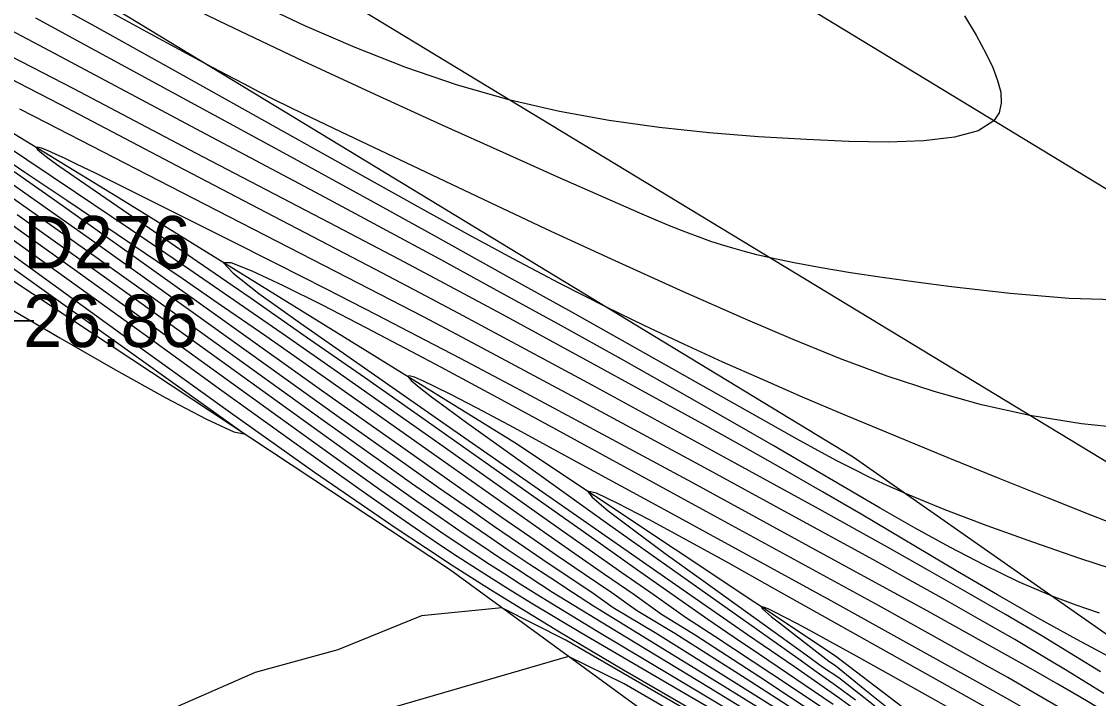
# Model space of a CAD drawing. Extents: x 2356077 to 2359823, y 225951 to 227822.
# Drawn here: x 2356489 to 2356540.3, y 227327.7 to 227360 of the extents above; entities that cross this region are included whole.
import ezdxf

# ---------------------------------------------------------------- set-up
doc = ezdxf.new("R2010")
doc.units = 0
for name, color, linetype in [('DTM Contours Major', 7, 'Continuous'), ('DTM Contours Minor', 7, 'Continuous'), ('Exist DTM Crownline', 7, 'Continuous'), ('Exist DTM Regular Point CELL', 7, 'Continuous'), ('Exist DTM Regular Point Cogo Elevation', 7, 'Continuous'), ('Exist DTM Regular Point Cogo Number', 7, 'Continuous'), ('Exist Roads EOP', 7, 'Continuous'), ('PH Exist DTM Breakline', 7, 'Continuous')]:
    doc.layers.add(name, color=color, linetype=linetype)

msp = doc.modelspace()

# ---------------------------------------------------------------- linework, layer by layer
at = {"layer": 'DTM Contours Major'}
for points in [[(2356541.622, 227333.644), (2356539.425, 227334.374), (2356537.196, 227335.142), (2356535.016, 227335.927), (2356532.964, 227336.708), (2356531.12, 227337.463), (2356530.235, 227337.854), (2356529.412, 227338.238), (2356528.631, 227338.624), (2356527.871, 227339.018), (2356527.11, 227339.427), (2356525.955, 227340.066), (2356518.48, 227344.278), (2356515.343, 227346.036), (2356512.075, 227347.86), (2356508.788, 227349.686), (2356505.591, 227351.451), (2356501.795, 227353.527), (2356492.468, 227358.61), (2356489.639, 227360.142)], [(2356540.42, 227327.183), (2356539.403, 227327.781), (2356538.375, 227328.375), (2356537.336, 227328.969), (2356536.282, 227329.565), (2356534.883, 227330.349), (2356532.009, 227331.942), (2356527.538, 227334.39), (2356520.938, 227337.985), (2356516.065, 227340.621), (2356513.037, 227342.245), (2356511.48, 227343.072), (2356509.884, 227343.914), (2356508.242, 227344.773), (2356505.891, 227345.99), (2356503.496, 227347.217), (2356501.118, 227348.425), (2356498.815, 227349.587), (2356494.676, 227351.661), (2356492.486, 227352.747), (2356491.578, 227353.188), (2356491.035, 227353.446), (2356490.568, 227353.662), (2356490.185, 227353.83), (2356489.897, 227353.943), (2356489.714, 227353.996), (2356489.646, 227353.983), (2356489.714, 227353.884), (2356489.926, 227353.701), (2356490.268, 227353.441), (2356490.729, 227353.109), (2356491.948, 227352.26), (2356495.057, 227350.126), (2356497.332, 227348.558), (2356499.851, 227346.815), (2356502.535, 227344.95), (2356505.306, 227343.017), (2356508.087, 227341.07), (2356510.798, 227339.161), (2356516.565, 227335.075), (2356518.337, 227333.823), (2356521.693, 227331.468), (2356522.935, 227330.617), (2356524.157, 227329.802), (2356527.661, 227327.416)], [(2356486.713, 227352.852), (2356489.333, 227351.009), (2356491.955, 227349.147), (2356494.546, 227347.294), (2356503.346, 227340.965), (2356506.203, 227338.927), (2356507.559, 227337.968), (2356508.881, 227337.041), (2356510.18, 227336.141), (2356511.173, 227335.46), (2356512.167, 227334.786), (2356513.171, 227334.114), (2356514.192, 227333.441), (2356515.236, 227332.763), (2356516.233, 227332.105), (2356522.308, 227328.367), (2356524.382, 227327.08)], [(2356488.037, 227346.502), (2356490.783, 227344.889), (2356493.442, 227343.365), (2356495.832, 227342.038), (2356497.77, 227341.015), (2356499.075, 227340.405), (2356499.564, 227340.316), (2356485.329, 227350.492)], [(2356533.057, 227318.89), (2356530.455, 227321.093), (2356529.82, 227321.83), (2356514.909, 227330.476), (2356511.858, 227332.014), (2356508.024, 227331.625), (2356504.035, 227330.014), (2356500.093, 227328.926), (2356496.11, 227327.175), (2356492.183, 227325.43), (2356488.37, 227323.972), (2356485.562, 227323.168), (2356482.844, 227322.567), (2356480.208, 227322.059), (2356477.647, 227321.533), (2356475.152, 227320.881), (2356472.716, 227319.993), (2356469.729, 227318.43), (2356466.769, 227316.422), (2356463.782, 227314.071), (2356460.714, 227311.474), (2356457.512, 227308.733), (2356454.123, 227305.947)]]:
    msp.add_lwpolyline(points, dxfattribs=at)
at = {"layer": 'DTM Contours Minor'}
for points in [[(2356541.589, 227346.691), (2356538.927, 227346.768), (2356536.11, 227347.006), (2356533.312, 227347.331), (2356531.615, 227347.55), (2356530.007, 227347.774), (2356528.496, 227348.002), (2356527.093, 227348.234), (2356525.81, 227348.471), (2356524.656, 227348.711), (2356524.024, 227348.859), (2356523.435, 227349.01), (2356522.878, 227349.166), (2356522.346, 227349.328), (2356521.829, 227349.499), (2356521.319, 227349.678), (2356520.639, 227349.934), (2356519.942, 227350.211), (2356519.217, 227350.513), (2356518.451, 227350.842), (2356516.749, 227351.589), (2356514.508, 227352.58), (2356511.917, 227353.734), (2356509.011, 227355.043), (2356505.824, 227356.501), (2356502.391, 227358.1), (2356498.745, 227359.834), (2356494.329, 227361.983)], [(2356542.615, 227335.394), (2356540.004, 227336.42), (2356537.884, 227337.262), (2356535.577, 227338.188), (2356533.145, 227339.174), (2356530.65, 227340.199), (2356528.153, 227341.242), (2356526.207, 227342.07), (2356524.293, 227342.9), (2356522.406, 227343.739), (2356520.539, 227344.592), (2356518.688, 227345.466), (2356516.847, 227346.365), (2356514.635, 227347.489), (2356512.427, 227348.651), (2356510.219, 227349.845), (2356508.009, 227351.064), (2356505.795, 227352.302), (2356498.687, 227356.289), (2356495.581, 227358.022), (2356492.328, 227359.827), (2356489.028, 227361.645)], [(2356540.408, 227328.965), (2356539.229, 227329.698), (2356537.621, 227330.67), (2356535.887, 227331.691), (2356534.06, 227332.746), (2356532.171, 227333.821), (2356530.25, 227334.902), (2356526.99, 227336.713), (2356522.996, 227338.908), (2356516.173, 227342.63), (2356514.065, 227343.772), (2356511.939, 227344.918), (2356509.805, 227346.06), (2356507.678, 227347.189), (2356505.83, 227348.16), (2356500.251, 227351.065), (2356496.385, 227353.083), (2356490.79, 227356.026), (2356488.796, 227357.068), (2356486.725, 227358.141), (2356484.568, 227359.245), (2356481.495, 227360.792)], [(2356541.101, 227329.529), (2356539.288, 227330.494), (2356537.412, 227331.54), (2356535.506, 227332.635), (2356533.603, 227333.75), (2356528.998, 227336.476), (2356527.155, 227337.551), (2356525.282, 227338.626), (2356523.339, 227339.722), (2356521.254, 227340.885), (2356519.083, 227342.085), (2356516.764, 227343.358), (2356514.343, 227344.678), (2356511.869, 227346.018), (2356509.39, 227347.349), (2356506.953, 227348.646), (2356503.645, 227350.386), (2356497.269, 227353.714), (2356491.447, 227356.771), (2356489.444, 227357.812), (2356487.398, 227358.864), (2356485.304, 227359.924), (2356482.938, 227361.1)], [(2356540.376, 227331.753), (2356539.248, 227332.135), (2356538.111, 227332.567), (2356536.505, 227333.259), (2356534.879, 227334.042), (2356533.237, 227334.901), (2356531.579, 227335.817), (2356529.909, 227336.774), (2356524.798, 227339.757), (2356522.978, 227340.809), (2356520.354, 227342.306), (2356517.575, 227343.87), (2356514.704, 227345.467), (2356511.803, 227347.065), (2356508.934, 227348.63), (2356506.161, 227350.128), (2356503.221, 227351.7), (2356497.542, 227354.718), (2356490.549, 227358.452), (2356488.189, 227359.699), (2356485.846, 227360.92)], [(2356541.99, 227340.539), (2356539.511, 227340.796), (2356537.052, 227341.191), (2356534.741, 227341.704), (2356532.477, 227342.335), (2356530.24, 227343.071), (2356528.008, 227343.9), (2356525.76, 227344.809), (2356523.476, 227345.783), (2356520.379, 227347.151), (2356517.265, 227348.563), (2356514.217, 227349.973), (2356511.32, 227351.332), (2356504.212, 227354.702), (2356502.378, 227355.584), (2356501.015, 227356.259), (2356500.303, 227356.619), (2356499.548, 227357.009), (2356498.729, 227357.439), (2356497.828, 227357.918), (2356495.127, 227359.38), (2356491.969, 227361.113)], [(2356533.931, 227360.26), (2356534.483, 227359.332), (2356534.965, 227358.444), (2356535.275, 227357.793), (2356535.511, 227357.18), (2356535.655, 227356.611), (2356535.685, 227356.095), (2356535.583, 227355.638), (2356535.329, 227355.249), (2356534.577, 227354.775), (2356533.445, 227354.466), (2356531.996, 227354.296), (2356530.295, 227354.239), (2356528.405, 227354.266), (2356526.39, 227354.352), (2356524.096, 227354.491), (2356521.749, 227354.68), (2356519.371, 227354.936), (2356516.983, 227355.27), (2356514.605, 227355.697), (2356512.261, 227356.231), (2356509.745, 227356.949), (2356507.282, 227357.794), (2356504.858, 227358.747), (2356502.461, 227359.79), (2356500.079, 227360.905)], [(2356540.576, 227327.918), (2356539.707, 227328.461), (2356538.824, 227329.003), (2356537.924, 227329.547), (2356536.324, 227330.494), (2356534.678, 227331.446), (2356532.999, 227332.4), (2356531.296, 227333.354), (2356529.581, 227334.304), (2356526.38, 227336.06), (2356521.925, 227338.484), (2356515.424, 227342.003), (2356511.83, 227343.932), (2356509.991, 227344.909), (2356508.122, 227345.893), (2356506.059, 227346.968), (2356503.967, 227348.049), (2356495.479, 227352.404), (2356490.177, 227355.132), (2356488.868, 227355.799)], [(2356486.866, 227354.97), (2356491.529, 227351.849), (2356494.101, 227350.113), (2356496.682, 227348.356), (2356499.129, 227346.674), (2356501.583, 227344.974), (2356504.025, 227343.27), (2356506.433, 227341.579), (2356508.788, 227339.919), (2356514.414, 227335.932), (2356516.02, 227334.798), (2356517.589, 227333.698), (2356519.129, 227332.631), (2356520.62, 227331.562), (2356522.019, 227330.668), (2356524.739, 227328.867), (2356527.392, 227327.093)], [(2356487.283, 227354.045), (2356489.115, 227352.804), (2356491.113, 227351.467), (2356493.019, 227350.182), (2356494.848, 227348.942), (2356496.614, 227347.736), (2356498.331, 227346.556), (2356500.599, 227344.984), (2356502.805, 227343.446), (2356504.947, 227341.942), (2356509.047, 227339.046), (2356513.92, 227335.6), (2356515.343, 227334.604), (2356516.754, 227333.626), (2356518.16, 227332.665), (2356519.483, 227331.705), (2356521.083, 227330.72), (2356524.12, 227328.745), (2356525.632, 227327.756), (2356527.13, 227326.766)], [(2356487.634, 227352.853), (2356489.917, 227351.247), (2356492.171, 227349.65), (2356494.387, 227348.071), (2356504.099, 227341.116), (2356507.296, 227338.846), (2356508.842, 227337.758), (2356510.36, 227336.697), (2356511.515, 227335.897), (2356512.663, 227335.107), (2356513.815, 227334.325), (2356514.978, 227333.546), (2356516.161, 227332.766), (2356517.179, 227332.036), (2356519.173, 227330.838), (2356522.907, 227328.503), (2356524.792, 227327.315)], [(2356488.596, 227352.83), (2356490.527, 227351.473), (2356494.261, 227348.827), (2356503.376, 227342.325), (2356507.025, 227339.736), (2356510.557, 227337.248), (2356511.882, 227336.322), (2356513.191, 227335.412), (2356514.493, 227334.516), (2356515.796, 227333.63), (2356517.108, 227332.752), (2356518.285, 227331.894), (2356520.109, 227330.799), (2356523.509, 227328.637), (2356525.21, 227327.547), (2356526.892, 227326.448), (2356528.667, 227325.395), (2356529.902, 227324.427), (2356531.181, 227323.461), (2356532.454, 227322.514), (2356533.695, 227321.564), (2356534.902, 227320.614), (2356535.995, 227319.683), (2356541.028, 227315.213)], [(2356488.124, 227350.556), (2356491.479, 227348.162), (2356494.837, 227345.745), (2356501.176, 227341.162), (2356503.964, 227339.152), (2356506.091, 227337.635), (2356507.078, 227336.94), (2356508.028, 227336.278), (2356508.954, 227335.643), (2356509.867, 227335.025), (2356510.57, 227334.558), (2356511.279, 227334.093), (2356511.998, 227333.628), (2356512.734, 227333.159), (2356513.492, 227332.683), (2356514.278, 227332.196), (2356516.438, 227330.886), (2356521.183, 227328.057), (2356523.648, 227326.576)], [(2356488.744, 227350.773), (2356491.734, 227348.645), (2356494.707, 227346.512), (2356502.906, 227340.598), (2356505.469, 227338.761), (2356506.659, 227337.916), (2356507.805, 227337.11), (2356508.921, 227336.335), (2356510.018, 227335.583), (2356510.861, 227335.013), (2356511.708, 227334.448), (2356512.567, 227333.883), (2356514.283, 227332.768), (2356517.33, 227330.892), (2356521.729, 227328.224), (2356523.995, 227326.837)], [(2356486.423, 227350.365), (2356490.453, 227347.46), (2356494.618, 227344.439), (2356498.812, 227341.414), (2356502.93, 227338.493), (2356506.866, 227335.785), (2356508.214, 227334.886), (2356509.538, 227334.021), (2356510.891, 227333.156), (2356511.568, 227332.731), (2356514.614, 227330.866), (2356517.666, 227329.058), (2356520.679, 227327.307), (2356523.605, 227325.612), (2356526.398, 227323.973), (2356529.013, 227322.389), (2356530.127, 227321.69), (2356531.198, 227320.999), (2356532.07, 227320.375), (2356533.323, 227319.314), (2356533.923, 227318.793), (2356539.719, 227313.647), (2356540.546, 227312.694)], [(2356487.411, 227350.387), (2356491.117, 227347.733), (2356494.855, 227345.032), (2356498.503, 227342.389), (2356501.936, 227339.91), (2356505.033, 227337.7), (2356506.691, 227336.538), (2356507.475, 227335.998), (2356508.238, 227335.478), (2356508.987, 227334.975), (2356509.729, 227334.485), (2356510.875, 227333.743), (2356512.045, 227333.006), (2356513.262, 227332.257), (2356515.626, 227330.843), (2356518.16, 227329.357), (2356520.799, 227327.82), (2356523.477, 227326.249)], [(2356538.371, 227327.306), (2356537.185, 227327.996), (2356535.992, 227328.681), (2356534.792, 227329.361), (2356532.347, 227330.728), (2356529.832, 227332.117), (2356521.611, 227336.617), (2356514.28, 227340.617), (2356511.644, 227342.047), (2356508.946, 227343.498), (2356507.572, 227344.229), (2356505.393, 227345.375), (2356503.305, 227346.451), (2356501.445, 227347.379), (2356499.949, 227348.078), (2356498.953, 227348.471), (2356498.593, 227348.479), (2356499.042, 227347.979), (2356500.266, 227347.013), (2356502.253, 227345.591), (2356509.522, 227340.52), (2356514.169, 227337.29), (2356520.507, 227332.873), (2356523.585, 227330.744), (2356525.814, 227329.206), (2356527.888, 227327.764), (2356528.94, 227327)], [(2356537.198, 227326.97), (2356535.839, 227327.746), (2356534.466, 227328.521), (2356532.013, 227329.888), (2356527.563, 227332.341), (2356519.958, 227336.511), (2356515.713, 227338.827), (2356512.445, 227340.595), (2356510.679, 227341.536), (2356509.365, 227342.22), (2356508.682, 227342.562), (2356508.118, 227342.831), (2356507.696, 227343.012), (2356507.44, 227343.09), (2356507.371, 227343.053), (2356507.532, 227342.865), (2356507.922, 227342.535), (2356508.512, 227342.08), (2356509.271, 227341.516), (2356510.172, 227340.862), (2356512.957, 227338.862), (2356516.909, 227336.042), (2356521.039, 227333.108), (2356525.974, 227329.615), (2356526.906, 227328.948), (2356527.822, 227328.288), (2356528.724, 227327.629)], [(2356535.84, 227326.761), (2356532.473, 227328.656), (2356524.774, 227332.975), (2356522.695, 227334.137), (2356520.688, 227335.248), (2356518.88, 227336.228), (2356517.401, 227336.998), (2356516.381, 227337.477), (2356515.947, 227337.585), (2356516.167, 227337.288), (2356516.935, 227336.645), (2356518.137, 227335.729), (2356519.656, 227334.613), (2356521.378, 227333.369), (2356524.795, 227330.915), (2356526.374, 227329.77), (2356527.152, 227329.2), (2356527.937, 227328.695), (2356529.645, 227327.329)], [(2356533.83, 227326.882), (2356532.055, 227327.88), (2356528.78, 227329.704), (2356526.551, 227330.929), (2356525.926, 227331.267), (2356525.378, 227331.557), (2356524.921, 227331.791), (2356524.57, 227331.958), (2356524.338, 227332.05), (2356524.241, 227332.058), (2356524.283, 227331.979), (2356524.448, 227331.821), (2356524.725, 227331.589), (2356525.099, 227331.292), (2356527.465, 227329.462), (2356527.782, 227329.264), (2356529.171, 227328.123), (2356530.68, 227326.914)], [(2356532.683, 227318.767), (2356530.517, 227320.601), (2356530.15, 227321.123), (2356527.696, 227322.582), (2356517.699, 227328.379), (2356515.039, 227329.69), (2356505.859, 227327.019), (2356477.438, 227312.958)]]:
    msp.add_lwpolyline(points, dxfattribs=at)
at = {"layer": 'Exist DTM Crownline'}
msp.add_lwpolyline([(2357542.756, 226741.609), (2357459.889, 226792.427), (2357374.177, 226844.74), (2357291.426, 226895.083), (2357208.118, 226946.275), (2357125.882, 226996.539), (2357045.017, 227045.595), (2356966.337, 227093.498), (2356883.413, 227143.712), (2356799.704, 227194.618), (2356722.637, 227241.528), (2356636.765, 227293.74), (2356553.053, 227344.465), (2356470.397, 227394.758), (2356383.201, 227447.638), (2356299.889, 227498.478), (2356223.248, 227545.375)], dxfattribs=at)
at = {"layer": 'Exist DTM Regular Point CELL'}
msp.add_lwpolyline([(2356486.533, 227348.705), (2356486.533, 227342.705), (2356486.533, 227345.705), (2356489.533, 227345.705), (2356483.533, 227345.705)], dxfattribs=at)
at = {"layer": 'Exist Roads EOP'}
msp.add_lwpolyline([(2357548.158, 226751.097), (2357551.518, 226748.955), (2357539.932, 226730.044), (2357536.732, 226732.588), (2357457.094, 226780.918), (2357368.575, 226834.971), (2357285.95, 226885.112), (2357202.56, 226936.462), (2357119.743, 226986.718), (2357040.047, 227034.838), (2356959.55, 227083.993), (2356876.77, 227134.388), (2356794.33, 227184.148), (2356716.529, 227232.438), (2356632.17, 227283.448), (2356547.589, 227334.799), (2356465.16, 227384.805), (2356376.528, 227438.798), (2356293.908, 227488.913), (2356217.843, 227535.566)], dxfattribs=at)
at = {"layer": 'PH Exist DTM Breakline'}
for points in [[(2356355.835, 227442.663), (2356385.919, 227425.194), (2356415.811, 227406.666), (2356443.878, 227390.232), (2356473.404, 227372.748), (2356501.523, 227355.674), (2356528.621, 227339.213), (2356543.022, 227329.128), (2356552.137, 227319.323), (2356555.467, 227312.405), (2356554.394, 227306.239), (2356549.197, 227297.848)], [(2356547.307, 227306.571), (2356542.97, 227311.331), (2356530.826, 227318.158), (2356509.361, 227333.838), (2356477.162, 227355.128), (2356446.028, 227372.373), (2356422.419, 227387.452), (2356398.28, 227401.994), (2356373.932, 227416.38), (2356353.156, 227428.562)], [(2356550.383, 227312.732), (2356539.292, 227320.934), (2356527.778, 227329.701), (2356512.485, 227339.892), (2356493.823, 227351.428), (2356470.72, 227365.56), (2356448.885, 227378.338), (2356429.689, 227389.183), (2356404.633, 227405.564)]]:
    msp.add_lwpolyline(points, dxfattribs=at)

# ---------------------------------------------------------------- texts
at = {"layer": 'Exist DTM Regular Point Cogo Elevation'}
msp.add_text('26.86', height=2.5, dxfattribs=at).set_placement((2356489.033, 227344.455))
at = {"layer": 'Exist DTM Regular Point Cogo Number'}
msp.add_text('D276', height=2.5, dxfattribs=at).set_placement((2356489.033, 227348.205))

doc.saveas('drawing.dxf')
